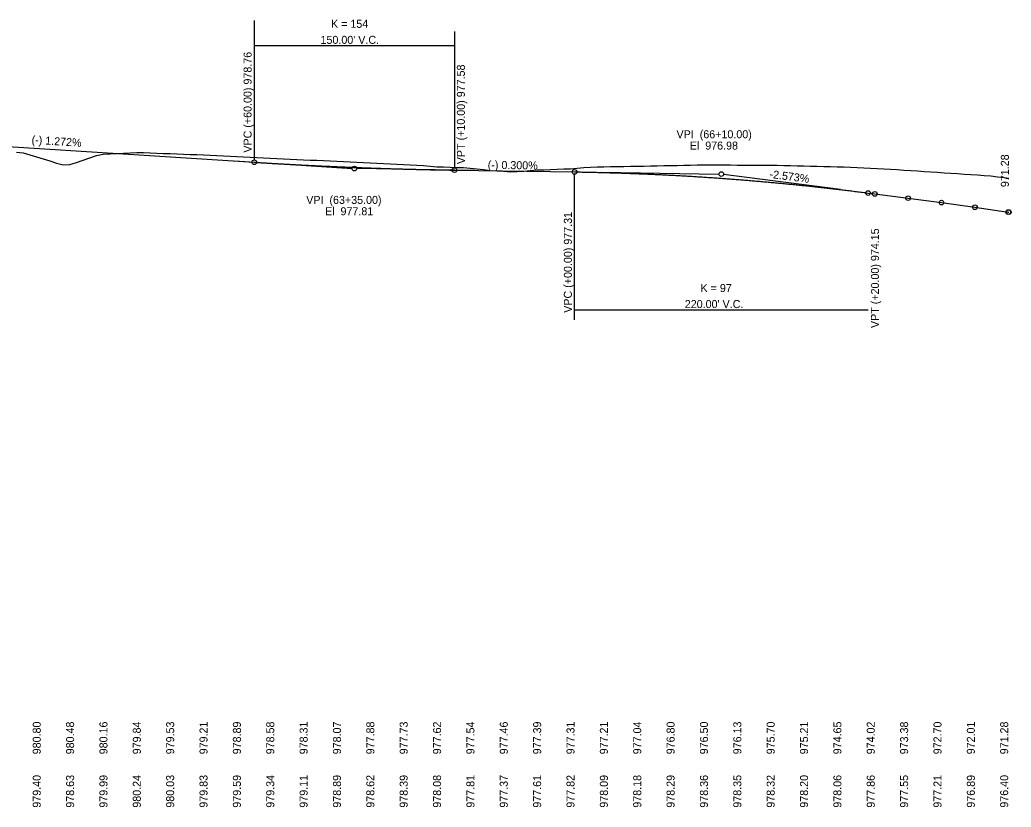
# Model space of a CAD drawing. Extents: x 126 to 16976848, y 7 to 12562190.
# Drawn here: x 16975266 to 16976009, y 12561517 to 12562108 of the extents above; entities that cross this region are included whole.
import ezdxf

# ---------------------------------------------------------------- set-up
doc = ezdxf.new("R2010")
doc.units = 0
for name, color, linetype in [('ANNOT_CONTOUR', 7, 'Continuous'), ('CLS_Shear_Line', 7, 'Continuous'), ('RD_EX_Conc-ZZ', 7, 'Continuous'), ('RD_HC_CL_50', 7, 'Continuous'), ('RD_HC_Points', 7, 'Continuous'), ('RD_PD_ConcMed', 7, 'Continuous'), ('RD_PD_SuperShp1', 7, 'Continuous')]:
    doc.layers.add(name, color=color, linetype=linetype)

msp = doc.modelspace()

# ---------------------------------------------------------------- linework, layer by layer
at = {"layer": 'CLS_Shear_Line'}
for p, q in [((16975441.51, 12562107.07), (16975441.51, 12562002.59)), ((16975591.51, 12562098.92), (16975591.51, 12561996.7)), ((16975441.51, 12562088.34), (16975591.51, 12562088.34)), ((16975681.51, 12561882.78), (16975681.51, 12561991.85)), ((16975681.51, 12561890.28), (16975901.51, 12561890.28))]:
    msp.add_line(p, q, dxfattribs=at)
for centre in [(16975441.51, 12562000.84), (16975591.51, 12561994.95), (16975681.51, 12561993.6), (16975901.51, 12561977.78)]:
    msp.add_circle(centre, 1.75, dxfattribs=at)
at = {"layer": 'RD_EX_Conc-ZZ'}
for p, q in [((16975426.69, 12562001.79), (16975514.76, 12561996.19)), ((16975606.5, 12561994.73), (16975518.26, 12561996.05)), ((16975701.52, 12561993.3), (16975789.76, 12561991.98)), ((16975880.77, 12561980.45), (16975793.24, 12561991.73))]:
    msp.add_line(p, q, dxfattribs=at)
for centre in [(16975516.51, 12561996.08), (16975791.51, 12561991.95), (16975906.51, 12561977.13), (16975931.51, 12561973.9), (16975956.51, 12561970.54), (16975981.51, 12561967.06), (16976006.51, 12561963.44), (16976006.97, 12561963.44)]:
    msp.add_circle(centre, 1.75, dxfattribs=at)
at = {"layer": 'RD_HC_Points'}
for points in [[(16975263.4, 12562008.48), (16975268.4, 12562007.79), (16975273.4, 12562006.49), (16975278.4, 12562004.98), (16975283.4, 12562003.44), (16975288.4, 12562001.86), (16975293.4, 12562000.26), (16975298.4, 12561998.98), (16975303.4, 12561999.27), (16975308.4, 12562000.68), (16975313.4, 12562002.37), (16975318.4, 12562004.07), (16975323.4, 12562005.77), (16975328.4, 12562006.77), (16975333.4, 12562007.08), (16975338.4, 12562007.4), (16975343.4, 12562007.66), (16975348.4, 12562007.91), (16975353.4, 12562008.16), (16975358.4, 12562008.16), (16975363.4, 12562007.91), (16975368.4, 12562007.66), (16975373.4, 12562007.47), (16975378.4, 12562007.3), (16975383.4, 12562007.12), (16975388.4, 12562006.95), (16975393.4, 12562006.76), (16975398.4, 12562006.55), (16975403.4, 12562006.33), (16975408.4, 12562006.11), (16975413.4, 12562005.88), (16975418.4, 12562005.66), (16975423.4, 12562005.41), (16975428.4, 12562005.15), (16975433.4, 12562004.9), (16975438.4, 12562004.64), (16975443.4, 12562004.39), (16975448.4, 12562004.13), (16975453.4, 12562003.86), (16975458.4, 12562003.62), (16975463.4, 12562003.4), (16975468.4, 12562003.18), (16975473.4, 12562002.96), (16975478.4, 12562002.73), (16975483.4, 12562002.51), (16975488.4, 12562002.3), (16975493.4, 12562002.07), (16975498.4, 12562001.85), (16975503.4, 12562001.63), (16975508.4, 12562001.4), (16975513.4, 12562001.17), (16975518.4, 12562000.94), (16975523.4, 12562000.69), (16975528.4, 12562000.3), (16975533.4, 12562000.05), (16975538.4, 12561999.81), (16975543.4, 12561999.58), (16975548.4, 12561999.34)], [(16975548.4, 12561999.34), (16975553.4, 12561999.1), (16975558.4, 12561998.86), (16975563.4, 12561998.61), (16975568.4, 12561998.37), (16975573.4, 12561997.92), (16975578.4, 12561997.51), (16975583.4, 12561997.35), (16975588.4, 12561997.18), (16975593.4, 12561997), (16975598.4, 12561996.83), (16975603.4, 12561996.37), (16975608.4, 12561995.88), (16975613.4, 12561995.4), (16975618.4, 12561994.63), (16975623.4, 12561994.34), (16975628.4, 12561994.04), (16975633.4, 12561993.74), (16975638.4, 12561993.91), (16975643.4, 12561994.27), (16975648.4, 12561994.63), (16975653.4, 12561995.25), (16975658.4, 12561995.2), (16975663.4, 12561995.47), (16975668.4, 12561995.73), (16975673.4, 12561995.8), (16975678.4, 12561995.86), (16975683.4, 12561996.51), (16975688.4, 12561996.95), (16975693.4, 12561997.17), (16975698.4, 12561997.34), (16975703.4, 12561997.44), (16975708.4, 12561997.53), (16975713.4, 12561997.63), (16975718.4, 12561997.72), (16975723.4, 12561997.81), (16975728.4, 12561997.89), (16975733.4, 12561997.98), (16975738.4, 12561998.06), (16975743.4, 12561998.18), (16975748.4, 12561998.28), (16975753.4, 12561998.39), (16975758.4, 12561998.5), (16975763.4, 12561998.6), (16975768.4, 12561998.7), (16975773.4, 12561998.79), (16975778.4, 12561998.84), (16975783.4, 12561998.83), (16975788.4, 12561998.83), (16975793.4, 12561998.81), (16975798.4, 12561998.79), (16975803.4, 12561998.77), (16975808.4, 12561998.75), (16975813.4, 12561998.73), (16975818.4, 12561998.71), (16975823.4, 12561998.68), (16975828.4, 12561998.66), (16975833.4, 12561998.59), (16975838.4, 12561998.52), (16975843.4, 12561998.39), (16975848.4, 12561998.25), (16975853.4, 12561998.11), (16975858.4, 12561997.98), (16975863.4, 12561997.84), (16975868.4, 12561997.7), (16975873.4, 12561997.56), (16975878.4, 12561997.42), (16975883.4, 12561997.28), (16975888.4, 12561997.14), (16975893.4, 12561996.94), (16975898.4, 12561996.71), (16975903.4, 12561996.48), (16975908.4, 12561996.24), (16975913.4, 12561995.93), (16975918.4, 12561995.61), (16975923.4, 12561995.3), (16975928.4, 12561994.98), (16975933.4, 12561994.66), (16975938.4, 12561994.34), (16975943.4, 12561994), (16975948.4, 12561993.64), (16975953.4, 12561993.28), (16975958.4, 12561992.93), (16975963.4, 12561992.61), (16975968.4, 12561992.29), (16975973.4, 12561991.98), (16975978.4, 12561991.66), (16975983.4, 12561991.34), (16975988.4, 12561991.02), (16975993.4, 12561990.55), (16975998.4, 12561989.96), (16976003.4, 12561989.37), (16976006.97, 12561988.95)]]:
    msp.add_lwpolyline(points, dxfattribs=at)
at = {"layer": 'RD_PD_ConcMed'}
for p, q in [((16975206.51, 12562015.79), (16975441.51, 12562000.84)), ((16975591.51, 12561994.95), (16975681.51, 12561993.6)), ((16975901.51, 12561977.78), (16975906.51, 12561977.13)), ((16975906.51, 12561977.13), (16975931.51, 12561973.9)), ((16975931.51, 12561973.9), (16975956.51, 12561970.54)), ((16975956.51, 12561970.54), (16975981.51, 12561967.06)), ((16975981.51, 12561967.06), (16976006.51, 12561963.44)), ((16976006.51, 12561963.44), (16976006.97, 12561963.44))]:
    msp.add_line(p, q, dxfattribs=at)
for points in [[(16975441.51, 12562000.84), (16975444.51, 12562000.66), (16975447.51, 12562000.47), (16975450.51, 12562000.29), (16975453.51, 12562000.1), (16975456.51, 12561999.93), (16975459.51, 12561999.75), (16975462.51, 12561999.58), (16975465.51, 12561999.41), (16975468.51, 12561999.25), (16975471.51, 12561999.08), (16975474.51, 12561998.92), (16975477.51, 12561998.77), (16975480.51, 12561998.61), (16975483.51, 12561998.46), (16975486.51, 12561998.31), (16975489.51, 12561998.17), (16975492.51, 12561998.02), (16975495.51, 12561997.88), (16975498.51, 12561997.75), (16975501.51, 12561997.61), (16975504.51, 12561997.48), (16975507.51, 12561997.35), (16975510.51, 12561997.23), (16975513.51, 12561997.11), (16975516.51, 12561996.99), (16975519.51, 12561996.87), (16975522.51, 12561996.76), (16975525.51, 12561996.65), (16975528.51, 12561996.54), (16975531.51, 12561996.43), (16975534.51, 12561996.33), (16975537.51, 12561996.23), (16975540.51, 12561996.14), (16975543.51, 12561996.04), (16975546.51, 12561995.95), (16975549.51, 12561995.87), (16975552.51, 12561995.78), (16975555.51, 12561995.7), (16975558.51, 12561995.62), (16975561.51, 12561995.55), (16975564.51, 12561995.47), (16975567.51, 12561995.4), (16975570.51, 12561995.34), (16975573.51, 12561995.27), (16975576.51, 12561995.21), (16975579.51, 12561995.15), (16975582.51, 12561995.1), (16975585.51, 12561995.05), (16975588.51, 12561995), (16975591.51, 12561994.95)], [(16975681.51, 12561993.6), (16975685.91, 12561993.53), (16975690.31, 12561993.45), (16975694.71, 12561993.36), (16975699.11, 12561993.26), (16975703.51, 12561993.15), (16975707.91, 12561993.02), (16975712.31, 12561992.89), (16975716.71, 12561992.75), (16975721.11, 12561992.6), (16975725.51, 12561992.44), (16975729.91, 12561992.27), (16975734.31, 12561992.09), (16975738.71, 12561991.9), (16975743.11, 12561991.69), (16975747.51, 12561991.48), (16975751.91, 12561991.26), (16975756.31, 12561991.03), (16975760.71, 12561990.79), (16975765.11, 12561990.54), (16975769.51, 12561990.28), (16975773.91, 12561990.01), (16975778.31, 12561989.72), (16975782.71, 12561989.43), (16975787.11, 12561989.13), (16975791.51, 12561988.82), (16975795.91, 12561988.5), (16975800.31, 12561988.17), (16975804.71, 12561987.83), (16975809.11, 12561987.47), (16975813.51, 12561987.11), (16975817.91, 12561986.74), (16975822.31, 12561986.36), (16975826.71, 12561985.97), (16975831.11, 12561985.57), (16975835.51, 12561985.15), (16975839.91, 12561984.73), (16975844.31, 12561984.3), (16975848.71, 12561983.86), (16975853.11, 12561983.41), (16975857.51, 12561982.95), (16975861.91, 12561982.47), (16975866.31, 12561981.99), (16975870.71, 12561981.5), (16975875.11, 12561981), (16975879.51, 12561980.49), (16975883.91, 12561979.97), (16975888.31, 12561979.43), (16975892.71, 12561978.89), (16975897.11, 12561978.34), (16975901.51, 12561977.78)]]:
    msp.add_spline(points, degree=3, dxfattribs=at)

# ---------------------------------------------------------------- texts
at = {"layer": 'ANNOT_CONTOUR'}
for s, p in [('979.40', (16975281.49, 12561517.03)), ('978.63', (16975306.49, 12561517.03)), ('979.99', (16975331.49, 12561517.03)), ('980.24', (16975356.49, 12561517.03)), ('980.03', (16975381.49, 12561517.03)), ('979.83', (16975406.49, 12561517.03)), ('979.59', (16975431.49, 12561517.03)), ('979.34', (16975456.49, 12561517.03)), ('979.11', (16975481.49, 12561517.03)), ('978.89', (16975506.49, 12561517.03)), ('978.62', (16975531.49, 12561517.03)), ('978.39', (16975556.49, 12561517.03)), ('978.08', (16975581.49, 12561517.03)), ('977.81', (16975606.49, 12561517.03)), ('977.37', (16975631.49, 12561517.03)), ('977.61', (16975656.49, 12561517.03)), ('977.82', (16975681.49, 12561517.03)), ('978.09', (16975706.49, 12561517.03)), ('978.18', (16975731.49, 12561517.03)), ('978.29', (16975756.49, 12561517.03)), ('978.36', (16975781.49, 12561517.03)), ('978.35', (16975806.49, 12561517.03)), ('978.32', (16975831.49, 12561517.03)), ('978.20', (16975856.49, 12561517.03)), ('978.06', (16975881.49, 12561517.03)), ('977.86', (16975906.49, 12561517.03)), ('977.55', (16975931.49, 12561517.03)), ('977.21', (16975956.49, 12561517.03)), ('976.89', (16975981.49, 12561517.03)), ('976.40', (16976006.49, 12561517.03))]:
    msp.add_text(s, height=6, rotation=90, dxfattribs=at).set_placement(p)
at = {"layer": 'CLS_Shear_Line'}
for s, p in [('K = 154', (16975499.03, 12562101.59)), ("150.00' V.C.", (16975491.15, 12562089.59)), ('K = 97', (16975775.92, 12561903.53)), ("220.00' V.C.", (16975764.14, 12561891.53))]:
    msp.add_text(s, height=6, dxfattribs=at).set_placement(p)
for s, p in [('VPC (+60.00) 978.76', (16975439.51, 12562008.01)), ('VPT (+10.00) 977.58', (16975599.33, 12561999.36)), ('VPC (+00.00) 977.31', (16975679.51, 12561887.98)), ('VPT (+20.00) 974.15', (16975909.63, 12561876.56))]:
    msp.add_text(s, height=6, rotation=90, dxfattribs=at).set_placement(p)
at = {"layer": 'RD_EX_Conc-ZZ'}
for s, p in [('VPI  (66+10.00)', (16975757.93, 12562018.82)), ('El  976.98', (16975767.85, 12562010.32)), ('VPI  (63+35.00)', (16975480.45, 12561969.6)), ('El  977.81', (16975494.54, 12561961.1))]:
    msp.add_text(s, height=6, dxfattribs=at).set_placement(p)
msp.add_text('971.28', height=6, rotation=90, dxfattribs=at).set_placement((16976006.97, 12561982.19))
at = {"layer": 'RD_HC_CL_50'}
for s, p in [('980.80', (16975281.49, 12561557.03)), ('980.48', (16975306.49, 12561557.03)), ('980.16', (16975331.49, 12561557.03)), ('979.84', (16975356.49, 12561557.03)), ('979.53', (16975381.49, 12561557.03)), ('979.21', (16975406.49, 12561557.03)), ('978.89', (16975431.49, 12561557.03)), ('978.58', (16975456.49, 12561557.03)), ('978.31', (16975481.49, 12561557.03)), ('978.07', (16975506.49, 12561557.03)), ('977.88', (16975531.49, 12561557.03)), ('977.73', (16975556.49, 12561557.03)), ('977.62', (16975581.49, 12561557.03)), ('977.54', (16975606.49, 12561557.03)), ('977.46', (16975631.49, 12561557.03)), ('977.39', (16975656.49, 12561557.03)), ('977.31', (16975681.49, 12561557.03)), ('977.21', (16975706.49, 12561557.03)), ('977.04', (16975731.49, 12561557.03)), ('976.80', (16975756.49, 12561557.03)), ('976.50', (16975781.49, 12561557.03)), ('976.13', (16975806.49, 12561557.03)), ('975.70', (16975831.49, 12561557.03)), ('975.21', (16975856.49, 12561557.03)), ('974.65', (16975881.49, 12561557.03)), ('974.02', (16975906.49, 12561557.03)), ('973.38', (16975931.49, 12561557.03)), ('972.70', (16975956.49, 12561557.03)), ('972.01', (16975981.49, 12561557.03)), ('971.28', (16976006.49, 12561557.03))]:
    msp.add_text(s, height=6, rotation=90, dxfattribs=at).set_placement(p)
at = {"layer": 'RD_PD_SuperShp1'}
for s, rotation, p in [('(-) 1.272%', 356.36178, (16975274.49, 12562014.77)), ('(-) 0.300%', 359.14063, (16975616.42, 12561995.94)), ('-2.573%', 352.65863, (16975827.37, 12561989.14))]:
    msp.add_text(s, height=6, rotation=rotation, dxfattribs=at).set_placement(p)

doc.saveas('drawing.dxf')
